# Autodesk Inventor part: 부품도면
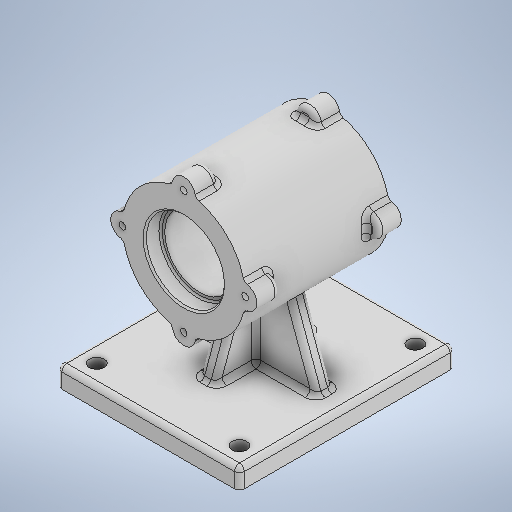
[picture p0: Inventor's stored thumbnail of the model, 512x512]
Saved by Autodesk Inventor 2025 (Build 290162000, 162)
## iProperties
Created: 2025-08
Part Number: 부품도면
Material: 일반
Document SubType Name: Modeling
Designer: infra04
Density: 1 g/cm^3
Appearance: 기본값
Author: infra04
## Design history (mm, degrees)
sketch "스케치1"
  geometry: L1 (55, 65)-(-55, 65); L2 (-55, 65)-(-55, -65); L3 (-55, -65)-(55, -65); L4 (55, -65)-(55, 65); L5 (55, 65)-(-55, -65); L6 (-55, 65)-(55, -65); 1 further point
  constraints: 12 end point, 2 midpoint, 2 parallel, 1 horizontal, 1 perpendicular
  dimensions: "d0" = 110 distance of L3.end L2.end; "d1" = 130 distance of L2.end L1.end
extrude "돌출1" new body sketch "스케치1" stored distance "d2" = 12; taper "d3" = 0 deg
sketch "스케치9"
  geometry: L1 (2.272, -0.317)-(52.134, -0.317); L2 (6, -65)-(6, 65) reference; L3 (6, -30.317)-(6, 29.683); L4 (49.764, 13.754)-(49.764, -14.388); L5 (49.764, -14.388)-(6, -30.317); L6 (49.764, 13.754)-(6, 29.683); 1 further point
  constraints: 10 end point, 2 point on line, 1 horizontal, 1 perpendicular, 1 other
  dimensions: "d17" = 60 distance of L3.start L3.end; "d18" = 110 deg angle of L2 L6
sketch "스케치16"
  geometry: L1 (55, -6)-(-55, -6) reference; C1 r 37 at (0, 76); 1 further point
  constraints: 1 centre point
  dimensions: "d36" = 74 diameter of C1; "d37" = 82 distance from line of L1 C1.centre
extrude "돌출10" join sketch "스케치16" stored distance "d38" = 87; taper "d39" = 0 deg
sketch "스케치18"
  geometry: C1 r 37 at (0, 76) reference; C2 r 23.5 at (0, 76); 1 further point
  constraints: 1 centre point, 1 coincident
  dimensions: "d51" = 47 diameter of C2
extrude "돌출11" cut sketch "스케치18" stored distance "d52" = 19; taper "d53" = 0 deg
sketch "스케치19"
  geometry: C1 r 23.5 at (0, 0) reference; C2 r 21 at (0, 0); 1 further point
  constraints: 1 centre point, 1 coincident
  dimensions: "d54" = 42 diameter of C2
extrude "돌출12" cut sketch "스케치19" distance "d55" = 162; taper "d56" = 0 deg
sketch "스케치20"
  geometry: 1 further point
sketch "스케치21"
  geometry: L1 (0, 76)-(75.102, 76); C1 r 37 at (0, 76) reference; C2 r 7 at (37, 76); C3 r 7 at (0, 113); C4 r 7 at (-37, 76); C5 r 7 at (0, 39); 1 further point
  constraints: 4 centre point, 2 end point, 1 horizontal, 9 other
  dimensions: "d57" = 14 diameter of C2; "d60" = 360 deg dimension on L1.start C2.centre (derived)
extrude "돌출13" join sketch "스케치21" distance "d62" = 14; taper "d63" = 0 deg
sketch "스케치22"
  geometry: L1 (37, 83.503)-(37, 63.191); L2 (30, 76)-(51.03, 76); C1 r 23.5 at (0, 76) reference; 6 further points
  constraints: 4 end point, 2 point on line, 1 coincident, 1 horizontal, 1 vertical, 5 other
  dimensions: "d66" = 360 deg dimension on C1.centre point (37, 76) (derived)
hole "구멍2" sketch "스케치22" at (0, 113), (-37, 76), (0, 39), (37, 76) diameter "d68" = 3.4; stored, may be unused: countersink angle "d72" = 90 deg, drill point angle "d74" = 118 deg; dims "d69" = 6, "d70" = 4, "d71" = 8, "d73" = 10
extrude "돌출14" join sketch "스케치9" stored distance "d75" = 10; taper "d76" = 0 deg
sketch "스케치23"
  geometry: L1 (43, 2.845)-(-43, 2.845); L2 (-43, 2.845)-(-25.154, 51.877); L3 (25.154, 51.877)-(43, 2.845); L4 (0, 0)-(0, 68.817); L5 (-25.154, 51.877)-(25.154, 51.877); L6 (55, 6)-(-55, 6) reference; 2 further points
  constraints: 10 end point, 2 horizontal, 1 other
  dimensions: "d77" = 86 distance of L1.start L1.end; "d78" = 110 deg angle of L6 L2
extrude "돌출15" join sketch "스케치23" stored distance "d79" = 10; taper "d80" = 0 deg
sketch "스케치24"
  geometry: 1 further point
fillet "모깎기2" dims "d87" = 3
fillet "모깎기4" dims "d89" = 3
chamfer "모따기1" distance "d90" = 1; stored, may be unused: second distance "d91" = 2, angle "d92" = 45 deg
chamfer "모따기2" distance "d93" = 1; stored, may be unused: second distance "d94" = 2, angle "d95" = 45 deg
fillet "모깎기5" dims "d96" = 1
sketch "스케치26"
  geometry: L1 (-55, -65)-(55, -65) reference; L2 (-74.738, 0)-(88.196, 0); L3 (0, -65)-(0, 90.487); 7 further points
  constraints: 4 end point, 3 symmetric about line, 1 horizontal, 1 midpoint, 1 vertical
  dimensions: "d97" = 12 distance from line of L1 point (-43, -53); "d105" = 86 distance of point (43, -53) point (-43, -53)
hole "구멍3" sketch "스케치26" at (-43, -53), (43, -53), (43, 53), (-43, 53) diameter "d98" = 9; stored, may be unused: countersink angle "d102" = 90 deg, drill point angle "d104" = 0 deg; dims "d99" = 6, "d100" = 4, "d101" = 8, "d103" = 12
fillet "모깎기6" dims "d106" = 3
node "솔리드1"
mirror "미러1"
mirror "미러2"
node "스케치 - 원형 패턴3" dims "d60" = 360 deg (derived)
node "스케치 - 원형 패턴4" dims "d66" = 360 deg (derived)
feature "A9D066F2-1C7D-4E18-AEED-F7BC21143FA4" dims "d68" = 3.4, "d69" = 6, "d70" = 4, "d71" = 8, "d72" = 90 deg, "d73" = 10, "d74" = 118 deg
